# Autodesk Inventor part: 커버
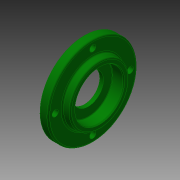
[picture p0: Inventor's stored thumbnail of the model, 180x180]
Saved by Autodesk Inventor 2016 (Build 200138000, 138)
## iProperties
Created: 2018-11
Part Number: 커버
Material: 알루미늄 6061
Document SubType Name: Modeling
Designer: mduedu
Density: 1 g/cm^3
Appearance: 진녹색
Author: mduedu
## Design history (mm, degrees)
sketch "스케치1"
  geometry: L1 (0, 0)-(3, 0); L2 (3, 0)-(3, 23.5); L3 (3, 23.5)-(0, 23.5); L4 (0, 23.5)-(0, 0); L5 (3, 0)-(9, 0); L6 (9, 0)-(9, 32); L7 (9, 32)-(3, 32); L8 (3, 32)-(3, 0); L9 (9, 0)-(14, 0); L10 (14, 0)-(14, 21.118); L11 (9, 22)-(9, 0); L12 (9, 22)-(14, 21.118)
  constraints: 24 end point, 5 parallel, 3 horizontal, 3 perpendicular
  dimensions: "d0" = 64 diameter of L7 L5; "d3" = 47 diameter of L3 L1; "d4" = 3 distance of L2.end L3.end; "d5" = 6 distance of L6.end L7.end; "d6" = 14 distance between parallel lines of L10 L4; "d37" = 44 diameter of L11.start L9; "d38" = 10 deg angle of L9 L12
revolve "회전1" sketch "스케치1" stored, may be unused: angle "d7" = 90 deg
sketch "스케치2"
  geometry: L1 (0, -23.5)-(0, 23.5) reference; L2 (0, 23.5)-(3, 23.5) reference; L3 (3, 23.5)-(3, 32) reference; L4 (3, 32)-(9, 32) reference; L5 (9, 32)-(9, 22) reference; L6 (9, -22)-(9, -32) reference; L7 (9, -32)-(3, -32) reference; L8 (3, -32)-(3, -23.5) reference; L9 (3, -23.5)-(0, -23.5) reference; L10 (0, 0)-(3, 0); L11 (3, 0)-(3, 20); L12 (3, 20)-(0, 20); L13 (0, 20)-(0, 0); L14 (3, 0)-(5.7, 0); L15 (5.7, 0)-(5.7, 12.5); L16 (5.7, 12.5)-(3, 12.5); L17 (3, 12.5)-(3, 0); L18 (5.7, 0)-(14, 0); L19 (14, 0)-(14, 17.5); L20 (14, 17.5)-(5.7, 17.5); L21 (5.7, 17.5)-(5.7, 0); L22 (9, 22)-(14, 21.118) reference; L23 (14, 21.118)-(14, -21.118) reference; L24 (14, -21.118)-(9, -22) reference
  constraints: 24 end point, 6 parallel, 3 horizontal, 3 perpendicular, 1 midpoint
  dimensions: "d8" = 35 diameter of L20 L18; "d10" = 25 diameter of L16 L14; "d11" = 40 diameter of L12 L10; "d12" = 3 distance of L11.end L12.end; "d13" = 8.3 distance of L19.end L20.end
revolve "회전2" sketch "스케치2" stored, may be unused: angle "d14" = 90 deg
fillet "모깎기1" dims "d15" = 0.3
chamfer "모따기1" distance "d16" = 0.8; stored, may be unused: second distance "d17" = 2, angle "d18" = 30 deg
fillet "모깎기2" dims "d19" = 1, "d35" = 3
chamfer "모따기2" distance "d20" = 0.5; stored, may be unused: second distance "d21" = 2, angle "d22" = 30 deg
sketch "스케치3" dims "d23" = 52
  geometry: 6 further points
  constraints: 2 vertical alignment, 1 coincident, 7 other
  dimensions: "d26" = 360 deg dimension on point (0, 0) point (0, 26) (derived)
sketch "스케치4" dims "d39" = 54
  geometry: C1 r 32 at (0, 0) reference; 5 further points
  constraints: 2 vertical alignment, 1 coincident, 7 other
  dimensions: "d43" = 360 deg dimension on C1.centre point (0, 27) (derived)
hole "구멍1" sketch "스케치4" at (0, 27), (-27, 0), (0, -27), (27, 0) diameter "d28" = 4.5; stored, may be unused: countersink angle "d32" = 90 deg, drill point angle "d34" = 0 deg; dims "d29" = 6, "d30" = 8, "d31" = 4.6, "d33" = 8
node "솔리드1"
node "절단 모서리 투영1"
